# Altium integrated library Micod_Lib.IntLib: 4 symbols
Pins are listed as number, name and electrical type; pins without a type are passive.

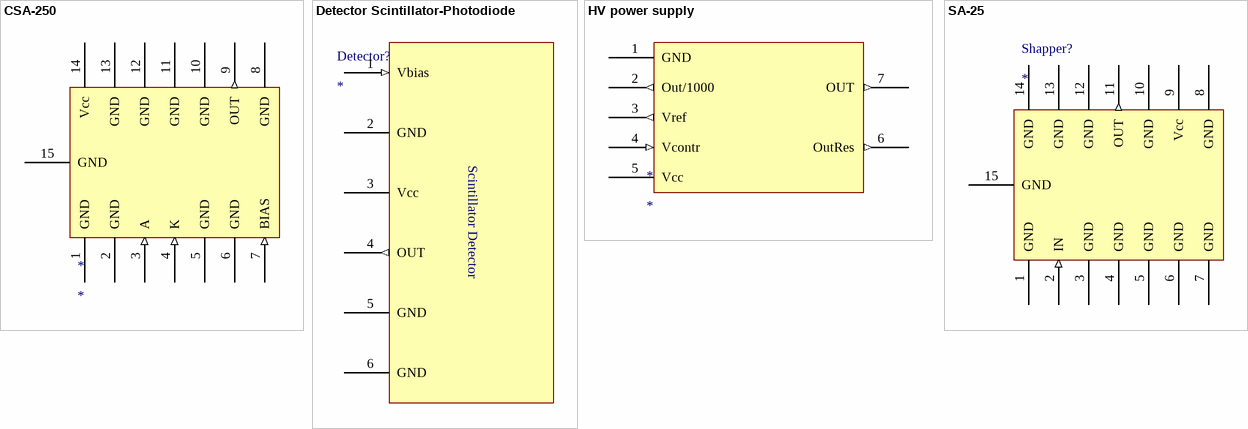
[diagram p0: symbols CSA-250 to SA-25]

## CSA-250
designator *
footprint 153.15-2
pins: 1 GND, 2 GND, 3 A (in), 4 K (in), 5 GND, 6 GND, 7 BIAS (in), 8 GND, 9 OUT (out), 10 GND, 11 GND, 12 GND, 13 GND, 14 Vcc (power), 15 GND

## Detector Scintillator-Photodiode
designator Detector?
footprint Detector
pins: 1 Vbias (in), 2 GND, 3 Vcc (power), 4 OUT (out), 5 GND, 6 GND

## HV power supply
designator *
footprint HV PS
pins: 1 GND, 2 Out/1000 (out), 3 Vref (out), 4 Vcontr (in), 5 Vcc (power), 6 OutRes (out), 7 OUT (out)

## SA-25
designator Shapper?
footprint 153.15-2
pins: 1 GND, 2 IN (in), 3 GND, 4 GND, 5 GND, 6 GND, 7 GND, 8 GND, 9 Vcc (power), 10 GND, 11 OUT (out), 12 GND, 13 GND, 14 GND, 15 GND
